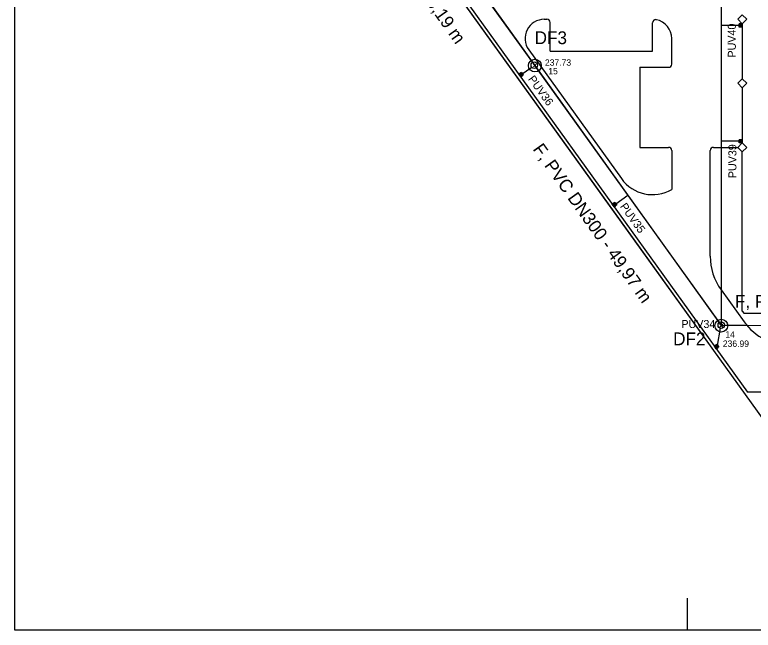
# Model space of a CAD drawing. Extents: x -264234 to -263604, y -1242346 to -1242049.
# Drawn here: x -264234.2 to -264118.9, y -1242345.9 to -1242249.8 of the extents above; entities that cross this region are included whole.
import ezdxf

# ---------------------------------------------------------------- set-up
doc = ezdxf.new("R2010")
doc.units = 0
for name, color, linetype in [('KFA_BODY_CISLO', 7, 'Continuous'), ('KFA_BODY_SYMBOL', 7, 'Continuous'), ('KFA_BODY_VYSKA', 7, 'Continuous'), ('KFA_DAZDOVA_KANALIZACIA_vetva_F', 7, 'Continuous'), ('KFA_DAZDOVA_KANALIZACIA_vetva_F_popis', 7, 'Continuous'), ('KFA_SITUACIA_DSP', 7, 'Continuous'), ('KFA_SO_40-2-II_DK_PRIPOJKY_UV_PROJEKT', 7, 'Continuous'), ('KFA_SO_40-2-II_DK_PRIPOJKY_UV_PROJEKT_popis', 7, 'Continuous'), ('KFA_SO_40-2-II_DK_UV_PROJEKT', 7, 'Continuous'), ('RAM_NA_TLAC_1-500', 7, 'Continuous')]:
    doc.layers.add(name, color=color, linetype=linetype)

msp = doc.modelspace()

# ---------------------------------------------------------------- linework, layer by layer
at = {"layer": 'KFA_BODY_SYMBOL'}
for p, q in [((-264153.18, -1242257.93), (-264152.73, -1242257.49)), ((-264152.73, -1242257.93), (-264153.18, -1242257.49)), ((-264124.06, -1242298.54), (-264123.61, -1242298.1)), ((-264123.61, -1242298.54), (-264124.06, -1242298.1))]:
    msp.add_line(p, q, dxfattribs=at)
at = {"layer": 'KFA_DAZDOVA_KANALIZACIA_vetva_F'}
for points in [[(-264177.27, -1242206.27), (-264123.92, -1242206.39), (-264123.86, -1242237.42), (-264123.84, -1242298.32)], [(-264182.21, -1242216.93), (-264152.95, -1242257.71), (-264123.84, -1242298.32)], [(-264123.84, -1242298.32), (-264095.25, -1242298.17), (-264095.21, -1242304.15)]]:
    msp.add_lwpolyline(points, dxfattribs=at)
for centre in [(-264152.95, -1242257.71), (-264123.84, -1242298.32)]:
    msp.add_circle(centre, 1, dxfattribs=at)
at = {"layer": 'KFA_SITUACIA_DSP'}
for p, q in [((-264204.69, -1242191.48), (-264115.87, -1242314.98)), ((-264204.08, -1242191.48), (-264119.75, -1242308.73)), ((-264181.95, -1242217.46), (-264153.34, -1242257.24)), ((-264123.85, -1242237.98), (-264123.85, -1242297.74)), ((-264151.48, -1242250.48), (-264151.07, -1242250.48)), ((-264150.57, -1242255.48), (-264150.57, -1242250.98)), ((-264134.57, -1242255.48), (-264134.57, -1242251.03)), ((-264121.06, -1242251.44), (-264123.85, -1242251.44)), ((-264120.86, -1242251.69), (-264120.86, -1242251.19)), ((-264120.86, -1242251.19), (-264120.57, -1242251.19)), ((-264120.86, -1242251.69), (-264120.57, -1242251.19)), ((-264120.86, -1242251.69), (-264120.57, -1242251.19)), ((-264120.57, -1242251.19), (-264120.86, -1242251.19)), ((-264120.86, -1242251.19), (-264120.86, -1242251.69)), ((-264120.57, -1242251.69), (-264120.86, -1242251.69)), ((-264120.57, -1242251.19), (-264120.57, -1242251.69)), ((-264120.57, -1242251.19), (-264120.57, -1242259.78)), ((-264131.57, -1242257.48), (-264131.57, -1242253.48)), ((-264153.92, -1242255.23), (-264139.44, -1242275.36)), ((-264150.57, -1242255.48), (-264134.57, -1242255.48)), ((-264155.08, -1242259.11), (-264153.45, -1242257.94)), ((-264154.92, -1242258.99), (-264153.45, -1242257.94)), ((-264152.76, -1242258.05), (-264124.15, -1242297.83)), ((-264152.76, -1242258.05), (-264124.15, -1242297.83)), ((-264136.57, -1242257.98), (-264136.57, -1242270.48)), ((-264136.57, -1242257.98), (-264132.07, -1242257.98)), ((-264155.46, -1242259.07), (-264155.23, -1242258.9)), ((-264155.17, -1242259.48), (-264155.46, -1242259.07)), ((-264155.23, -1242258.9), (-264154.94, -1242259.31)), ((-264155.23, -1242258.9), (-264155.17, -1242259.48)), ((-264155.23, -1242258.9), (-264155.17, -1242259.48)), ((-264154.94, -1242259.31), (-264155.23, -1242258.9)), ((-264154.94, -1242259.31), (-264155.17, -1242259.48)), ((-264155.17, -1242259.48), (-264154.94, -1242259.31)), ((-264120.57, -1242261.19), (-264120.57, -1242269.77)), ((-264121.06, -1242269.53), (-264123.85, -1242269.53)), ((-264120.86, -1242269.78), (-264120.86, -1242269.28)), ((-264120.86, -1242269.28), (-264120.57, -1242269.28)), ((-264120.86, -1242269.78), (-264120.57, -1242269.28)), ((-264120.86, -1242269.78), (-264120.57, -1242269.28)), ((-264120.57, -1242269.28), (-264120.86, -1242269.28)), ((-264120.86, -1242269.28), (-264120.86, -1242269.78)), ((-264120.57, -1242269.78), (-264120.86, -1242269.78)), ((-264120.57, -1242269.28), (-264120.57, -1242269.78)), ((-264136.57, -1242270.48), (-264132.07, -1242270.48)), ((-264131.57, -1242270.98), (-264131.57, -1242277.06)), ((-264125.57, -1242287.47), (-264125.57, -1242270.98)), ((-264125.07, -1242270.48), (-264121.27, -1242270.48)), ((-264140.32, -1242279.29), (-264138.45, -1242277.94)), ((-264140.87, -1242279.37), (-264140.63, -1242279.2)), ((-264140.58, -1242279.78), (-264140.87, -1242279.37)), ((-264140.63, -1242279.2), (-264140.34, -1242279.61)), ((-264140.63, -1242279.2), (-264140.58, -1242279.78)), ((-264140.63, -1242279.2), (-264140.58, -1242279.78)), ((-264140.34, -1242279.61), (-264140.63, -1242279.2)), ((-264140.34, -1242279.61), (-264140.58, -1242279.78)), ((-264140.58, -1242279.78), (-264140.34, -1242279.61)), ((-264123.87, -1242292.72), (-264120.27, -1242297.74)), ((-264120.57, -1242296.04), (-264120.28, -1242296.43)), ((-264124.44, -1242301.41), (-264123.95, -1242298.73)), ((-264123.35, -1242298.24), (-264120.15, -1242298.24)), ((-264124.92, -1242301.54), (-264124.69, -1242301.37)), ((-264124.63, -1242301.94), (-264124.92, -1242301.54)), ((-264124.69, -1242301.37), (-264124.4, -1242301.77)), ((-264124.69, -1242301.37), (-264124.63, -1242301.94)), ((-264124.69, -1242301.37), (-264124.63, -1242301.94)), ((-264124.4, -1242301.77), (-264124.69, -1242301.37)), ((-264124.4, -1242301.77), (-264124.63, -1242301.94)), ((-264124.63, -1242301.94), (-264124.4, -1242301.77)), ((-264050.53, -1242308.73), (-264119.75, -1242308.73))]:
    msp.add_line(p, q, dxfattribs=at)
for points in [[(-264204.69, -1242191.48), (-264137.78, -1242284.52), (-264125.58, -1242301.48)], [(-264120.57, -1242296.04), (-264120.57, -1242271.19), (-264120.57, -1242271.19)], [(-263965.14, -1242296.43), (-264120.02, -1242296.43), (-264120.28, -1242296.43)]]:
    msp.add_lwpolyline(points, dxfattribs=at)
for points in [[(-264120.57, -1242249.78), (-264119.86, -1242250.48), (-264120.57, -1242251.19), (-264121.27, -1242250.48)], [(-264120.57, -1242259.78), (-264119.86, -1242260.48), (-264120.57, -1242261.19), (-264121.27, -1242260.48)], [(-264120.57, -1242269.78), (-264119.86, -1242270.48), (-264120.57, -1242271.19), (-264121.27, -1242270.48)]]:
    msp.add_lwpolyline(points, close=True, dxfattribs=at)
for centre, radius in [((-264120.96, -1242251.44), 0.1), ((-264153.05, -1242257.64), 0.5), ((-264155, -1242259.05), 0.1), ((-264120.96, -1242269.53), 0.1), ((-264140.4, -1242279.35), 0.1), ((-264123.85, -1242298.24), 0.5), ((-264124.46, -1242301.51), 0.1)]:
    msp.add_circle(centre, radius, dxfattribs=at)
for centre, radius, start, end in [((-264151.48, -1242253.48), 3, 90, 215.724), ((-264151.07, -1242250.98), 0.5, 0, 90), ((-264134.07, -1242251.03), 0.5, 78.463, 180), ((-264134.57, -1242253.48), 3, 0, 78.463), ((-264132.07, -1242257.48), 0.5, 270, 0), ((-264132.07, -1242270.98), 0.5, 0, 90), ((-264125.07, -1242270.98), 0.5, 90, 180), ((-264134.57, -1242271.86), 6, 215.724, 300), ((-264116.57, -1242287.47), 9, 180, 215.724), ((-264112.96, -1242292.48), 9, 215.724, 270)]:
    msp.add_arc(centre, radius, start, end, dxfattribs=at)
at = {"layer": 'KFA_SO_40-2-II_DK_PRIPOJKY_UV_PROJEKT'}
for points in [[(-264121.06, -1242251.44), (-264123.85, -1242251.44)], [(-264154.92, -1242258.99), (-264153.45, -1242257.94)], [(-264121.06, -1242269.53), (-264123.85, -1242269.53)], [(-264140.32, -1242279.29), (-264138.45, -1242277.94)], [(-264124.44, -1242301.41), (-264123.95, -1242298.73)]]:
    msp.add_lwpolyline(points, dxfattribs=at)
at = {"layer": 'KFA_SO_40-2-II_DK_UV_PROJEKT'}
for points in [[(-264121.07, -1242251.69), (-264121.07, -1242251.19), (-264120.57, -1242251.19), (-264120.57, -1242251.69), (-264121.07, -1242251.69), (-264120.57, -1242251.19), (-264121.07, -1242251.19), (-264120.57, -1242251.69)], [(-264155.17, -1242259.48), (-264155.46, -1242259.07), (-264155.06, -1242258.78), (-264154.77, -1242259.19), (-264155.17, -1242259.48), (-264155.06, -1242258.78), (-264155.46, -1242259.07), (-264154.77, -1242259.19)], [(-264121.07, -1242269.78), (-264121.07, -1242269.28), (-264120.57, -1242269.28), (-264120.57, -1242269.78), (-264121.07, -1242269.78), (-264120.57, -1242269.28), (-264121.07, -1242269.28), (-264120.57, -1242269.78)], [(-264140.58, -1242279.78), (-264140.87, -1242279.37), (-264140.46, -1242279.08), (-264140.17, -1242279.48), (-264140.58, -1242279.78), (-264140.46, -1242279.08), (-264140.87, -1242279.37), (-264140.17, -1242279.48)], [(-264124.63, -1242301.94), (-264124.92, -1242301.54), (-264124.52, -1242301.25), (-264124.23, -1242301.65), (-264124.63, -1242301.94), (-264124.52, -1242301.25), (-264124.92, -1242301.54), (-264124.23, -1242301.65)]]:
    msp.add_lwpolyline(points, dxfattribs=at)
at = {"layer": 'RAM_NA_TLAC_1-500'}
msp.add_line((-264129.18, -1242340.88), (-264129.18, -1242345.88), dxfattribs=at)
msp.add_lwpolyline([(-264234.18, -1242048.88), (-263604.18, -1242048.88), (-263604.18, -1242345.88), (-264234.18, -1242345.88)], close=True, dxfattribs=at)

# ---------------------------------------------------------------- texts
at = {"layer": 'KFA_BODY_CISLO'}
for s, p in [('15', (-264150.85, -1242259.08)), ('14', (-264123.2, -1242300.19))]:
    msp.add_text(s, height=1, dxfattribs=at).set_placement(p)
at = {"layer": 'KFA_BODY_VYSKA'}
for s, p in [('237.73', (-264151.38, -1242257.73)), ('236.99', (-264123.6, -1242301.64))]:
    msp.add_text(s, height=1, dxfattribs=at).set_placement(p)
at = {"layer": 'KFA_DAZDOVA_KANALIZACIA_vetva_F_popis'}
for s, p in [('F, PVC DN300 - 50,19 m', (-264182.5, -1242230.3)), ('F, PVC DN300 - 49,97 m', (-264153.36, -1242270.77))]:
    msp.add_text(s, height=2, rotation=305.4236, dxfattribs=at).set_placement(p)
for s, p in [('DF3', (-264152.99, -1242254.36)), ('F, PVC DN300 - 28,59 m', (-264121.71, -1242295.51)), ('DF2', (-264131.36, -1242301.38))]:
    msp.add_text(s, height=2, dxfattribs=at).set_placement(p)
at = {"layer": 'KFA_SO_40-2-II_DK_PRIPOJKY_UV_PROJEKT_popis'}
for s, rotation, p in [('PUV40', 90, (-264121.57, -1242256.45)), ('PUV36', 305.724, (-264154.07, -1242259.82)), ('PUV39', 90, (-264121.48, -1242275.29)), ('PUV35', 305.724, (-264139.72, -1242279.72))]:
    msp.add_text(s, height=1.25, rotation=rotation, dxfattribs=at).set_placement(p)
msp.add_text('PUV34', height=1.25, dxfattribs=at).set_placement((-264130.07, -1242298.69))

doc.saveas('drawing.dxf')
